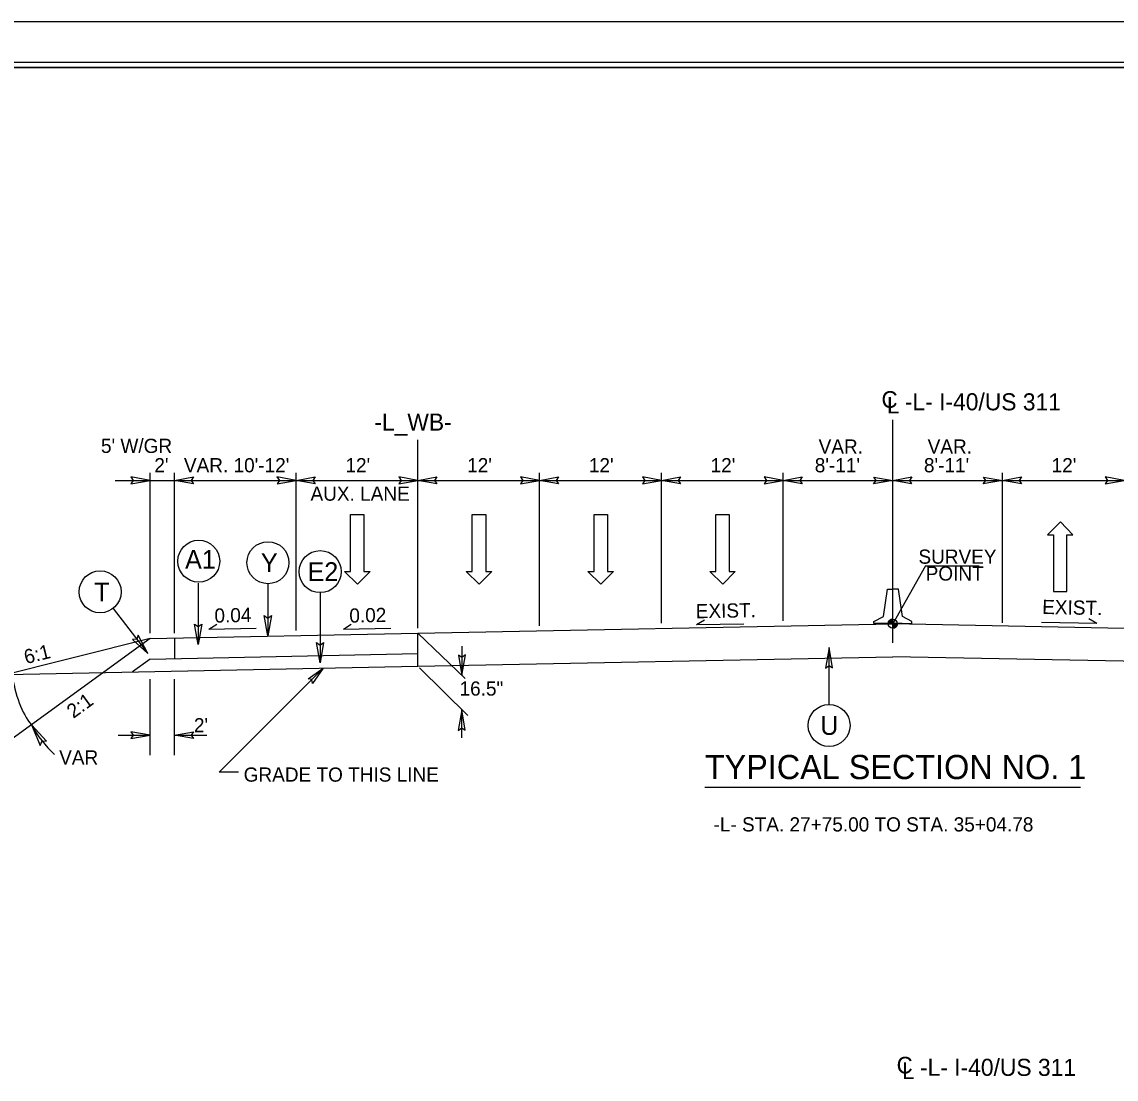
# Model space of a CAD drawing. Extents: x 1640342 to 1730599, y 538663 to 843747.
# Drawn here: x 1729953.2 to 1730061, y 539740.3 to 539844.5 of the extents above; entities that cross this region are included whole.
import ezdxf

# ---------------------------------------------------------------- set-up
doc = ezdxf.new("R2010")
doc.units = 0
for name, color, linetype in [('Default', 7, 'Continuous'), ('Prop Dimension Text', 7, 'Continuous'), ('Prop Terminator CELL', 7, 'Continuous'), ('Sheet Clip Boundary CELL', 7, 'Continuous'), ('Sheet Layout Plan Border', 7, 'Continuous'), ('Sheet Plan CELL', 7, 'Continuous'), ('Sheet Plan Layout CELL', 7, 'Continuous'), ('Sheet Plot Border Inside CELL', 7, 'Continuous'), ('Sheet Plot Border Outside CELL', 7, 'Continuous'), ('Typical Grade Point Symbol CELL', 7, 'Continuous'), ('Typical Hinge Slope Interstate CELL', 7, 'Continuous'), ('Typical ID Circle CELL', 7, 'Continuous'), ('Typical Pavement Slope CELL', 7, 'Continuous'), ('Typical Pavement Slope Information CELL', 7, 'Continuous'), ('Typical Terminator CELL', 7, 'Continuous'), ('Typical Text Centerline CELL', 7, 'Continuous'), ('Typical Text General CELL', 7, 'Continuous'), ('Typical Text Grade Point CELL', 7, 'Continuous'), ('Typical Text ID Circle CELL', 7, 'Continuous'), ('Typical Text Label CELL', 7, 'Continuous')]:
    doc.layers.add(name, color=color, linetype=linetype)

msp = doc.modelspace()

# ---------------------------------------------------------------- linework, layer by layer
at = {"layer": 'Default'}
for p, q in [((1729992.2, 539784.74), (1729992.2, 539803.3)), ((1729965.8, 539784.26), (1729965.8, 539800.04)), ((1729968.2, 539784.26), (1729968.2, 539800.04)), ((1729980.2, 539784.5), (1729980.2, 539800.04)), ((1729992.2, 539784.74), (1729992.2, 539800.04)), ((1730004.2, 539784.98), (1730004.2, 539800.04)), ((1730016.22, 539785.22), (1730016.22, 539800.04)), ((1730028.22, 539785.46), (1730028.22, 539800.04)), ((1730049.82, 539785.26), (1730049.82, 539800.04)), ((1729962.35, 539799.3), (1729968.22, 539799.3)), ((1729968.22, 539799.3), (1729980.22, 539799.3)), ((1729980.22, 539799.3), (1729992.22, 539799.3)), ((1729992.22, 539799.3), (1730004.22, 539799.3)), ((1730004.22, 539799.3), (1730016.22, 539799.3)), ((1730016.22, 539799.3), (1730028.22, 539799.3)), ((1730028.22, 539799.3), (1730039.01, 539799.3)), ((1730039.01, 539799.3), (1730049.84, 539799.3)), ((1730049.84, 539799.3), (1730061.84, 539799.3)), ((1729985.57, 539790.33), (1729985.57, 539795.93)), ((1729985.57, 539795.93), (1729986.89, 539795.93)), ((1729986.89, 539795.93), (1729986.89, 539790.33)), ((1729997.57, 539790.33), (1729997.57, 539795.93)), ((1729997.57, 539795.93), (1729998.89, 539795.93)), ((1729998.89, 539795.93), (1729998.89, 539790.33)), ((1730009.57, 539790.33), (1730009.57, 539795.93)), ((1730009.57, 539795.93), (1730010.89, 539795.93)), ((1730010.89, 539795.93), (1730010.89, 539790.33)), ((1730021.57, 539790.33), (1730021.57, 539795.93)), ((1730021.57, 539795.93), (1730022.89, 539795.93)), ((1730022.89, 539795.93), (1730022.89, 539790.33)), ((1730055.54, 539795.21), (1730054.26, 539793.95)), ((1730056.78, 539793.95), (1730055.54, 539795.21)), ((1730054.26, 539793.95), (1730054.86, 539793.95)), ((1730054.86, 539793.95), (1730054.86, 539788.36)), ((1730056.18, 539788.36), (1730056.18, 539793.95)), ((1730056.18, 539793.95), (1730056.78, 539793.95)), ((1729986.25, 539789.07), (1729984.97, 539790.33)), ((1729984.97, 539790.33), (1729985.57, 539790.33)), ((1729987.49, 539790.33), (1729986.25, 539789.07)), ((1729986.89, 539790.33), (1729987.49, 539790.33)), ((1729998.25, 539789.07), (1729996.97, 539790.33)), ((1729996.97, 539790.33), (1729997.57, 539790.33)), ((1729999.49, 539790.33), (1729998.25, 539789.07)), ((1729998.89, 539790.33), (1729999.49, 539790.33)), ((1730010.25, 539789.07), (1730008.97, 539790.33)), ((1730008.97, 539790.33), (1730009.57, 539790.33)), ((1730011.49, 539790.33), (1730010.25, 539789.07)), ((1730010.89, 539790.33), (1730011.49, 539790.33)), ((1730022.25, 539789.07), (1730020.97, 539790.33)), ((1730020.97, 539790.33), (1730021.57, 539790.33)), ((1730023.49, 539790.33), (1730022.25, 539789.07)), ((1730022.89, 539790.33), (1730023.49, 539790.33)), ((1730054.86, 539788.36), (1730056.18, 539788.36)), ((1729992.21, 539784.24), (1729996.86, 539779.78)), ((1729996.55, 539782.97), (1729996.55, 539780.08)), ((1729992.36, 539780.84), (1729997.12, 539776.14)), ((1729965.8, 539772.22), (1729965.8, 539779.71)), ((1729968.2, 539772.22), (1729968.2, 539779.71)), ((1729996.53, 539773.94), (1729996.53, 539776.69)), ((1729962.66, 539774.18), (1729965.8, 539774.18)), ((1729968.2, 539774.18), (1729971.39, 539774.18))]:
    msp.add_line(p, q, dxfattribs=at)
for points in [[(1729963.92, 539798.98), (1729965.8, 539799.3), (1729963.91, 539799.64), (1729964.15, 539799.3)], [(1729970.07, 539798.98), (1729968.2, 539799.3), (1729970.08, 539799.64), (1729969.84, 539799.3)], [(1729978.32, 539798.98), (1729980.2, 539799.3), (1729978.31, 539799.64), (1729978.55, 539799.3)], [(1729982.07, 539798.98), (1729980.2, 539799.3), (1729982.08, 539799.64), (1729981.84, 539799.3)], [(1729990.32, 539798.98), (1729992.2, 539799.3), (1729990.31, 539799.64), (1729990.55, 539799.3)], [(1729994.07, 539798.98), (1729992.2, 539799.3), (1729994.08, 539799.64), (1729993.84, 539799.3)], [(1730002.32, 539798.98), (1730004.2, 539799.3), (1730002.31, 539799.64), (1730002.55, 539799.3)], [(1730006.07, 539798.98), (1730004.2, 539799.3), (1730006.08, 539799.64), (1730005.84, 539799.3)], [(1730014.34, 539798.98), (1730016.22, 539799.3), (1730014.33, 539799.64), (1730014.57, 539799.3)], [(1730018.09, 539798.98), (1730016.22, 539799.3), (1730018.1, 539799.64), (1730017.86, 539799.3)], [(1730026.34, 539798.98), (1730028.22, 539799.3), (1730026.33, 539799.64), (1730026.57, 539799.3)], [(1730030.09, 539798.98), (1730028.22, 539799.3), (1730030.1, 539799.64), (1730029.86, 539799.3)], [(1730037.14, 539799.63), (1730039.01, 539799.3), (1730037.13, 539798.97), (1730037.37, 539799.3)], [(1730040.88, 539798.98), (1730039.01, 539799.3), (1730040.89, 539799.64), (1730040.66, 539799.3)], [(1730047.95, 539799.63), (1730049.82, 539799.3), (1730047.94, 539798.97), (1730048.18, 539799.3)], [(1730051.7, 539798.98), (1730049.82, 539799.3), (1730051.71, 539799.64), (1730051.47, 539799.3)], [(1730059.97, 539798.98), (1730061.84, 539799.3), (1730059.96, 539799.64), (1730060.2, 539799.3)], [(1729955.6, 539773.61), (1729954.1, 539775.2), (1729954.98, 539773.18), (1729955.15, 539773.63)], [(1729955.6, 539773.61), (1729954.1, 539775.2), (1729954.98, 539773.18), (1729955.15, 539773.63)], [(1729963.92, 539773.86), (1729965.8, 539774.18), (1729963.91, 539774.51), (1729964.15, 539774.18)], [(1729970.07, 539773.86), (1729968.2, 539774.18), (1729970.08, 539774.51), (1729969.84, 539774.18)]]:
    msp.add_lwpolyline(points, close=True, dxfattribs=at)
at = {"layer": 'Prop Terminator CELL'}
msp.add_lwpolyline([(1729981.38, 539779.76), (1729982.88, 539780.81), (1729981.82, 539779.3), (1729981.76, 539779.69)], close=True, dxfattribs=at)
at = {"layer": 'Sheet Clip Boundary CELL'}
msp.add_lwpolyline([(1729883.99, 539630), (1730163.99, 539630), (1730163.99, 539797.7), (1730126.14, 539797.7), (1730126.14, 539840), (1729883.99, 539840)], close=True, dxfattribs=at)
at = {"layer": 'Sheet Layout Plan Border'}
msp.add_lwpolyline([(1729883.99, 539630), (1730163.99, 539630), (1730163.99, 539797.7), (1730126.14, 539797.7), (1730126.14, 539840), (1729883.99, 539840)], close=True, dxfattribs=at)
at = {"layer": 'Sheet Plan CELL'}
for points in [[(1730174, 539840), (1729873.99, 539840), (1729873.99, 539630), (1730173.99, 539630)], [(1729873.99, 539630), (1729873.99, 539840), (1730133.98, 539840), (1730133.99, 539809.99), (1730173.99, 539809.99), (1730173.99, 539630)]]:
    msp.add_lwpolyline(points, close=True, dxfattribs=at)
at = {"layer": 'Sheet Plan Layout CELL'}
msp.add_lwpolyline([(1729873.99, 539840), (1729873.99, 539630), (1730173.99, 539630), (1730173.99, 539797.7), (1730126.14, 539797.7), (1730126.14, 539840)], close=True, dxfattribs=at)
at = {"layer": 'Sheet Plot Border Inside CELL'}
msp.add_lwpolyline([(1729843.29, 539629.5), (1730176.49, 539629.5), (1730176.49, 539840.5), (1729843.29, 539840.5)], close=True, dxfattribs=at)
at = {"layer": 'Sheet Plot Border Outside CELL'}
msp.add_lwpolyline([(1729840.69, 539625.5), (1730177.39, 539625.5), (1730177.39, 539844.5), (1729840.69, 539844.5)], close=True, dxfattribs=at)
at = {"layer": 'Typical Grade Point Symbol CELL'}
for p, q in [((1730039.01, 539785.18), (1730039.01, 539785.62)), ((1730038.56, 539785.18), (1730039.01, 539785.18)), ((1730039.01, 539784.73), (1730039.01, 539785.18)), ((1730039.46, 539785.18), (1730039.01, 539785.18)), ((1730039.01, 539785.18), (1730039.01, 539784.73))]:
    msp.add_line(p, q, dxfattribs=at)
for points in [[(1730038.61, 539785.38), (1730038.61, 539785.18)], [(1730038.62, 539785.4), (1730038.62, 539785.18)], [(1730038.63, 539785.41), (1730038.63, 539785.18)], [(1730038.64, 539785.43), (1730038.64, 539785.18)], [(1730038.65, 539785.44), (1730038.65, 539785.18)], [(1730038.66, 539785.45), (1730038.66, 539785.18)], [(1730038.67, 539785.46), (1730038.67, 539785.18)], [(1730038.68, 539785.48), (1730038.68, 539785.18)], [(1730038.68, 539785.47), (1730038.68, 539785.18)], [(1730038.69, 539785.49), (1730038.69, 539785.18)], [(1730038.7, 539785.5), (1730038.7, 539785.18)], [(1730038.71, 539785.51), (1730038.71, 539785.18)], [(1730038.72, 539785.52), (1730038.72, 539785.18)], [(1730038.73, 539785.52), (1730038.73, 539785.18)], [(1730038.74, 539785.53), (1730038.74, 539785.18)], [(1730038.75, 539785.54), (1730038.75, 539785.18)], [(1730038.76, 539785.55), (1730038.76, 539785.18)], [(1730038.76, 539785.54), (1730038.76, 539785.18)], [(1730038.77, 539785.56), (1730038.77, 539785.18)], [(1730038.78, 539785.56), (1730038.78, 539785.18)], [(1730038.79, 539785.57), (1730038.79, 539785.18)], [(1730038.8, 539785.57), (1730038.8, 539785.18)], [(1730038.81, 539785.58), (1730038.81, 539785.18)], [(1730038.82, 539785.58), (1730038.82, 539785.18)], [(1730038.83, 539785.58), (1730038.83, 539785.18)], [(1730038.84, 539785.59), (1730038.84, 539785.18)], [(1730038.85, 539785.6), (1730038.85, 539785.18)], [(1730038.85, 539785.59), (1730038.85, 539785.18)], [(1730038.86, 539785.6), (1730038.86, 539785.18)], [(1730038.87, 539785.6), (1730038.87, 539785.18)], [(1730038.88, 539785.6), (1730038.88, 539785.18)], [(1730038.89, 539785.61), (1730038.89, 539785.18)], [(1730038.9, 539785.61), (1730038.9, 539785.18)], [(1730038.91, 539785.61), (1730038.91, 539785.18)], [(1730038.92, 539785.61), (1730038.92, 539785.18)], [(1730038.93, 539785.62), (1730038.93, 539785.18)], [(1730038.93, 539785.62), (1730038.93, 539785.18)], [(1730038.94, 539785.62), (1730038.94, 539785.18)], [(1730038.95, 539785.62), (1730038.95, 539785.18)], [(1730038.96, 539785.62), (1730038.96, 539785.18)], [(1730038.97, 539785.62), (1730038.97, 539785.18)], [(1730038.98, 539785.62), (1730038.98, 539785.18)], [(1730038.99, 539785.62), (1730038.99, 539785.18)], [(1730039, 539785.62), (1730039, 539785.18)], [(1730039.01, 539785.62), (1730039.01, 539785.62), (1730039.01, 539785.18)], [(1730038.57, 539785.24), (1730038.57, 539785.18)], [(1730038.58, 539785.29), (1730038.58, 539785.18)], [(1730038.59, 539785.34), (1730038.59, 539785.18)], [(1730038.59, 539785.32), (1730038.59, 539785.18)], [(1730038.6, 539785.36), (1730038.6, 539785.18)], [(1730039.02, 539785.18), (1730039.02, 539784.73), (1730039.02, 539784.73)], [(1730039.03, 539785.18), (1730039.03, 539784.73)], [(1730039.04, 539785.18), (1730039.04, 539784.73)], [(1730039.04, 539785.18), (1730039.04, 539784.73)], [(1730039.05, 539785.18), (1730039.05, 539784.73)], [(1730039.06, 539785.18), (1730039.06, 539784.73)], [(1730039.07, 539785.18), (1730039.07, 539784.73)], [(1730039.08, 539785.18), (1730039.08, 539784.73)], [(1730039.09, 539785.18), (1730039.09, 539784.74)], [(1730039.1, 539785.18), (1730039.1, 539784.74)], [(1730039.11, 539785.18), (1730039.11, 539784.74)], [(1730039.12, 539785.18), (1730039.12, 539784.74)], [(1730039.12, 539785.18), (1730039.12, 539784.74)], [(1730039.13, 539785.18), (1730039.13, 539784.75)], [(1730039.14, 539785.18), (1730039.14, 539784.75)], [(1730039.15, 539785.18), (1730039.15, 539784.75)], [(1730039.16, 539785.18), (1730039.16, 539784.75)], [(1730039.17, 539785.18), (1730039.17, 539784.76)], [(1730039.18, 539785.18), (1730039.18, 539784.76)], [(1730039.19, 539785.18), (1730039.19, 539784.77)], [(1730039.2, 539785.18), (1730039.2, 539784.77)], [(1730039.21, 539785.18), (1730039.21, 539784.78)], [(1730039.21, 539785.18), (1730039.21, 539784.77)], [(1730039.22, 539785.18), (1730039.22, 539784.78)], [(1730039.23, 539785.18), (1730039.23, 539784.79)], [(1730039.24, 539785.18), (1730039.24, 539784.79)], [(1730039.25, 539785.18), (1730039.25, 539784.8)], [(1730039.26, 539785.18), (1730039.26, 539784.8)], [(1730039.27, 539785.18), (1730039.27, 539784.81)], [(1730039.28, 539785.18), (1730039.28, 539784.82)], [(1730039.29, 539785.18), (1730039.29, 539784.83)], [(1730039.29, 539785.18), (1730039.29, 539784.82)], [(1730039.3, 539785.18), (1730039.3, 539784.84)], [(1730039.31, 539785.18), (1730039.31, 539784.85)], [(1730039.32, 539785.18), (1730039.32, 539784.85)], [(1730039.33, 539785.18), (1730039.33, 539784.86)], [(1730039.34, 539785.18), (1730039.34, 539784.87)], [(1730039.35, 539785.18), (1730039.35, 539784.88)], [(1730039.36, 539785.18), (1730039.36, 539784.89)], [(1730039.37, 539785.18), (1730039.37, 539784.92)], [(1730039.37, 539785.18), (1730039.37, 539784.9)], [(1730039.38, 539785.18), (1730039.38, 539784.93)], [(1730039.39, 539785.18), (1730039.39, 539784.94)], [(1730039.4, 539785.18), (1730039.4, 539784.96)], [(1730039.41, 539785.18), (1730039.41, 539784.98)], [(1730039.42, 539785.18), (1730039.42, 539785)], [(1730039.43, 539785.18), (1730039.43, 539785.02)], [(1730039.44, 539785.18), (1730039.44, 539785.04)], [(1730039.45, 539785.18), (1730039.45, 539785.07)], [(1730039.46, 539785.18), (1730039.46, 539785.13)]]:
    msp.add_lwpolyline(points, dxfattribs=at)
msp.add_circle((1730039.01, 539785.18), 0.447, dxfattribs=at)
for start, end in [(90.0093, 180.0093), (270.0093, 0.0093)]:
    msp.add_arc((1730039.01, 539785.18), 0.447, start, end, dxfattribs=at)
at = {"layer": 'Typical Hinge Slope Interstate CELL'}
msp.add_arc((1729964.64, 539781.07), 12.06, 209.0778, 226.6941, dxfattribs=at)
msp.add_arc((1729964.64, 539781.07), 12.06, 209.0778, 226.6941, dxfattribs=at)
msp.add_ellipse((1729958.25, 539785.67), major_axis=(-1.85, -11.92), ratio=0.5, start_param=5.254774, end_param=5.856596, dxfattribs=at)
at = {"layer": 'Typical ID Circle CELL'}
for p, q in [((1729970.54, 539789.18), (1729970.54, 539783.13)), ((1729977.42, 539789.12), (1729977.42, 539783.98)), ((1729982.57, 539788.24), (1729982.57, 539781.31)), ((1729962.15, 539786.68), (1729965.58, 539782.24)), ((1730032.74, 539777.22), (1730032.74, 539782.83))]:
    msp.add_line(p, q, dxfattribs=at)
for centre in [(1729970.6, 539791.34), (1729977.42, 539791.19), (1729982.57, 539790.31), (1729960.88, 539788.32), (1730032.74, 539775.15)]:
    msp.add_circle(centre, 2.07, dxfattribs=at)
at = {"layer": 'Typical Pavement Slope CELL'}
for p, q in [((1730038.09, 539785.9), (1730038.49, 539788.6)), ((1730038.49, 539788.6), (1730039.03, 539788.6)), ((1730039.57, 539788.6), (1730039.03, 539788.6)), ((1730039.97, 539785.9), (1730039.57, 539788.6)), ((1729992.2, 539784.24), (1730039.01, 539785.18)), ((1730085.82, 539784.24), (1730039.01, 539785.18)), ((1729965.8, 539783.72), (1729948.57, 539779.41)), ((1729965.8, 539783.72), (1729950.69, 539772.73)), ((1729965.8, 539783.72), (1729992.19, 539784.24)), ((1729968.2, 539783.76), (1729968.2, 539781.75)), ((1729992.2, 539780.99), (1729992.2, 539784.24)), ((1729965.8, 539781.7), (1729992.2, 539782.23)), ((1729965.8, 539781.7), (1729964.06, 539780.44)), ((1729992.2, 539780.99), (1730039.01, 539781.93)), ((1730073.17, 539781.25), (1730039.01, 539781.93)), ((1729951.67, 539780.18), (1729992.2, 539780.99))]:
    msp.add_line(p, q, dxfattribs=at)
for points in [[(1730039.94, 539785.2), (1730037.15, 539785.2), (1730037.15, 539785.41), (1730038.09, 539785.9)], [(1730038.12, 539785.2), (1730040.91, 539785.2), (1730040.91, 539785.41), (1730039.97, 539785.9)]]:
    msp.add_lwpolyline(points, dxfattribs=at)
at = {"layer": 'Typical Pavement Slope Information CELL'}
for p, q in [((1730019.67, 539785.09), (1730020.45, 539785.56)), ((1730059.12, 539785.19), (1730058.34, 539785.67)), ((1729971.6, 539784.65), (1729972.39, 539785.12)), ((1729971.6, 539784.65), (1729976.26, 539784.74)), ((1729984.86, 539784.65), (1729985.64, 539785.12)), ((1729984.86, 539784.65), (1729989.52, 539784.74)), ((1730019.67, 539785.09), (1730024.33, 539785.18)), ((1730059.12, 539785.19), (1730053.67, 539785.3))]:
    msp.add_line(p, q, dxfattribs=at)
at = {"layer": 'Typical Terminator CELL'}
for p, q in [((1729972.62, 539770.56), (1729982.88, 539780.81)), ((1729974.53, 539770.56), (1729972.62, 539770.56))]:
    msp.add_line(p, q, dxfattribs=at)
for points in [[(1729977.77, 539785.99), (1729977.42, 539783.98), (1729977.06, 539786), (1729977.42, 539785.74)], [(1729970.89, 539785.14), (1729970.54, 539783.13), (1729970.19, 539785.15), (1729970.54, 539784.9)], [(1729964.08, 539783.62), (1729965.58, 539782.24), (1729964.63, 539784.06), (1729964.5, 539783.64)], [(1729982.91, 539783.32), (1729982.57, 539781.31), (1729982.21, 539783.33), (1729982.57, 539783.08)], [(1730033.09, 539780.82), (1730032.74, 539782.83), (1730032.39, 539780.81), (1730032.74, 539781.07)], [(1729996.2, 539782.09), (1729996.55, 539780.08), (1729996.91, 539782.1), (1729996.55, 539781.84)], [(1729996.87, 539774.68), (1729996.53, 539776.69), (1729996.17, 539774.67), (1729996.53, 539774.92)]]:
    msp.add_lwpolyline(points, close=True, dxfattribs=at)
at = {"layer": 'Typical Text Centerline CELL'}
msp.add_line((1730039.01, 539783.29), (1730039.01, 539805.29), dxfattribs=at)
at = {"layer": 'Typical Text Grade Point CELL'}
for q in [(1730039.01, 539785.18), (1730047.55, 539790.9)]:
    msp.add_line((1730042.25, 539790.9), q, dxfattribs=at)
at = {"layer": 'Typical Text Label CELL'}
msp.add_line((1730020.49, 539769.06), (1730057.53, 539769.06), dxfattribs=at)

# ---------------------------------------------------------------- texts
at = {"layer": 'Default'}
for s, p in [('16.5"', (1729996.31, 539778.09)), ("2'", (1729970.12, 539774.47))]:
    msp.add_text(s, height=1.4, dxfattribs=at).set_placement(p)
at = {"layer": 'Prop Dimension Text'}
for s, rotation, p in [('6:1', 14.0362, (1729953.57, 539781.19)), ('2:1', 36.0298, (1729958.24, 539775.79))]:
    msp.add_text(s, height=1.4, rotation=rotation, dxfattribs=at).set_placement(p)
msp.add_text('VAR', height=1.4, dxfattribs=at).set_placement((1729956.84, 539771.3))
at = {"layer": 'Typical Pavement Slope CELL'}
msp.add_text('-L- STA. 27+75.00 TO STA. 35+04.78', height=1.4, dxfattribs=at).set_placement((1730021.35, 539764.7))
at = {"layer": 'Typical Pavement Slope Information CELL'}
for s, p in [("5' W/GR", (1729960.96, 539802.01)), ('VAR.', (1730031.71, 539801.94)), ('VAR.', (1730042.46, 539801.94)), ("2'", (1729966.22, 539800.1)), ("VAR. 10'-12'", (1729969.14, 539800.1)), ("12'", (1729985.06, 539800.1)), ("12'", (1729997.06, 539800.1)), ("12'", (1730009.06, 539800.1)), ("12'", (1730021.06, 539800.1)), ("8'-11'", (1730031.33, 539800.1)), ("8'-11'", (1730042.09, 539800.1)), ("12'", (1730054.68, 539800.1)), ('AUX. LANE', (1729981.62, 539797.3))]:
    msp.add_text(s, height=1.4, dxfattribs=at).set_placement(p)
for s, rotation, p in [('EXIST.', 358.8543, (1730053.74, 539786.14)), ('0.04', 1.1457, (1729972.16, 539785.28)), ('0.02', 1.1457, (1729985.46, 539785.28)), ('EXIST.', 1.1457, (1730019.61, 539785.71))]:
    msp.add_text(s, height=1.4, rotation=rotation, dxfattribs=at).set_placement(p)
at = {"layer": 'Typical Text Centerline CELL'}
for s, height, rotation, p in [('C', 1.64, 0.0443, (1730037.91, 539806.46)), ('L', 1.64, 359.9912, (1730038.45, 539805.9)), ('-L- I-40/US 311', 1.683, 359.9417, (1730040.21, 539806.22)), ('C', 1.64, 0.0443, (1730039.4, 539740.85)), ('-L- I-40/US 311', 1.683, 359.9417, (1730041.7, 539740.62)), ('L', 1.64, 359.9912, (1730039.94, 539740.3))]:
    msp.add_text(s, height=height, rotation=rotation, dxfattribs=at).set_placement(p)
msp.add_text('-L_WB-', height=1.683, dxfattribs=at).set_placement((1729987.91, 539804.21))
at = {"layer": 'Typical Text General CELL'}
msp.add_text('GRADE TO THIS LINE', height=1.4, rotation=360, dxfattribs=at).set_placement((1729975.03, 539769.61))
at = {"layer": 'Typical Text Grade Point CELL'}
for s, p in [('SURVEY', (1730041.55, 539791.09)), ('POINT', (1730042.26, 539789.43))]:
    msp.add_text(s, height=1.4, rotation=359.9998, dxfattribs=at).set_placement(p)
at = {"layer": 'Typical Text ID Circle CELL'}
for s, height, p in [('A1', 1.854, (1729969.25, 539790.59)), ('Y', 1.85, (1729976.73, 539790.26)), ('E2', 1.854, (1729981.32, 539789.38)), ('T', 1.85, (1729960.29, 539787.39)), ('U', 1.85, (1730031.87, 539774.22))]:
    msp.add_text(s, height=height, dxfattribs=at).set_placement(p)
at = {"layer": 'Typical Text Label CELL'}
msp.add_text('TYPICAL SECTION NO. 1', height=2.3871, rotation=360, dxfattribs=at).set_placement((1730020.49, 539769.86))

doc.saveas('drawing.dxf')
